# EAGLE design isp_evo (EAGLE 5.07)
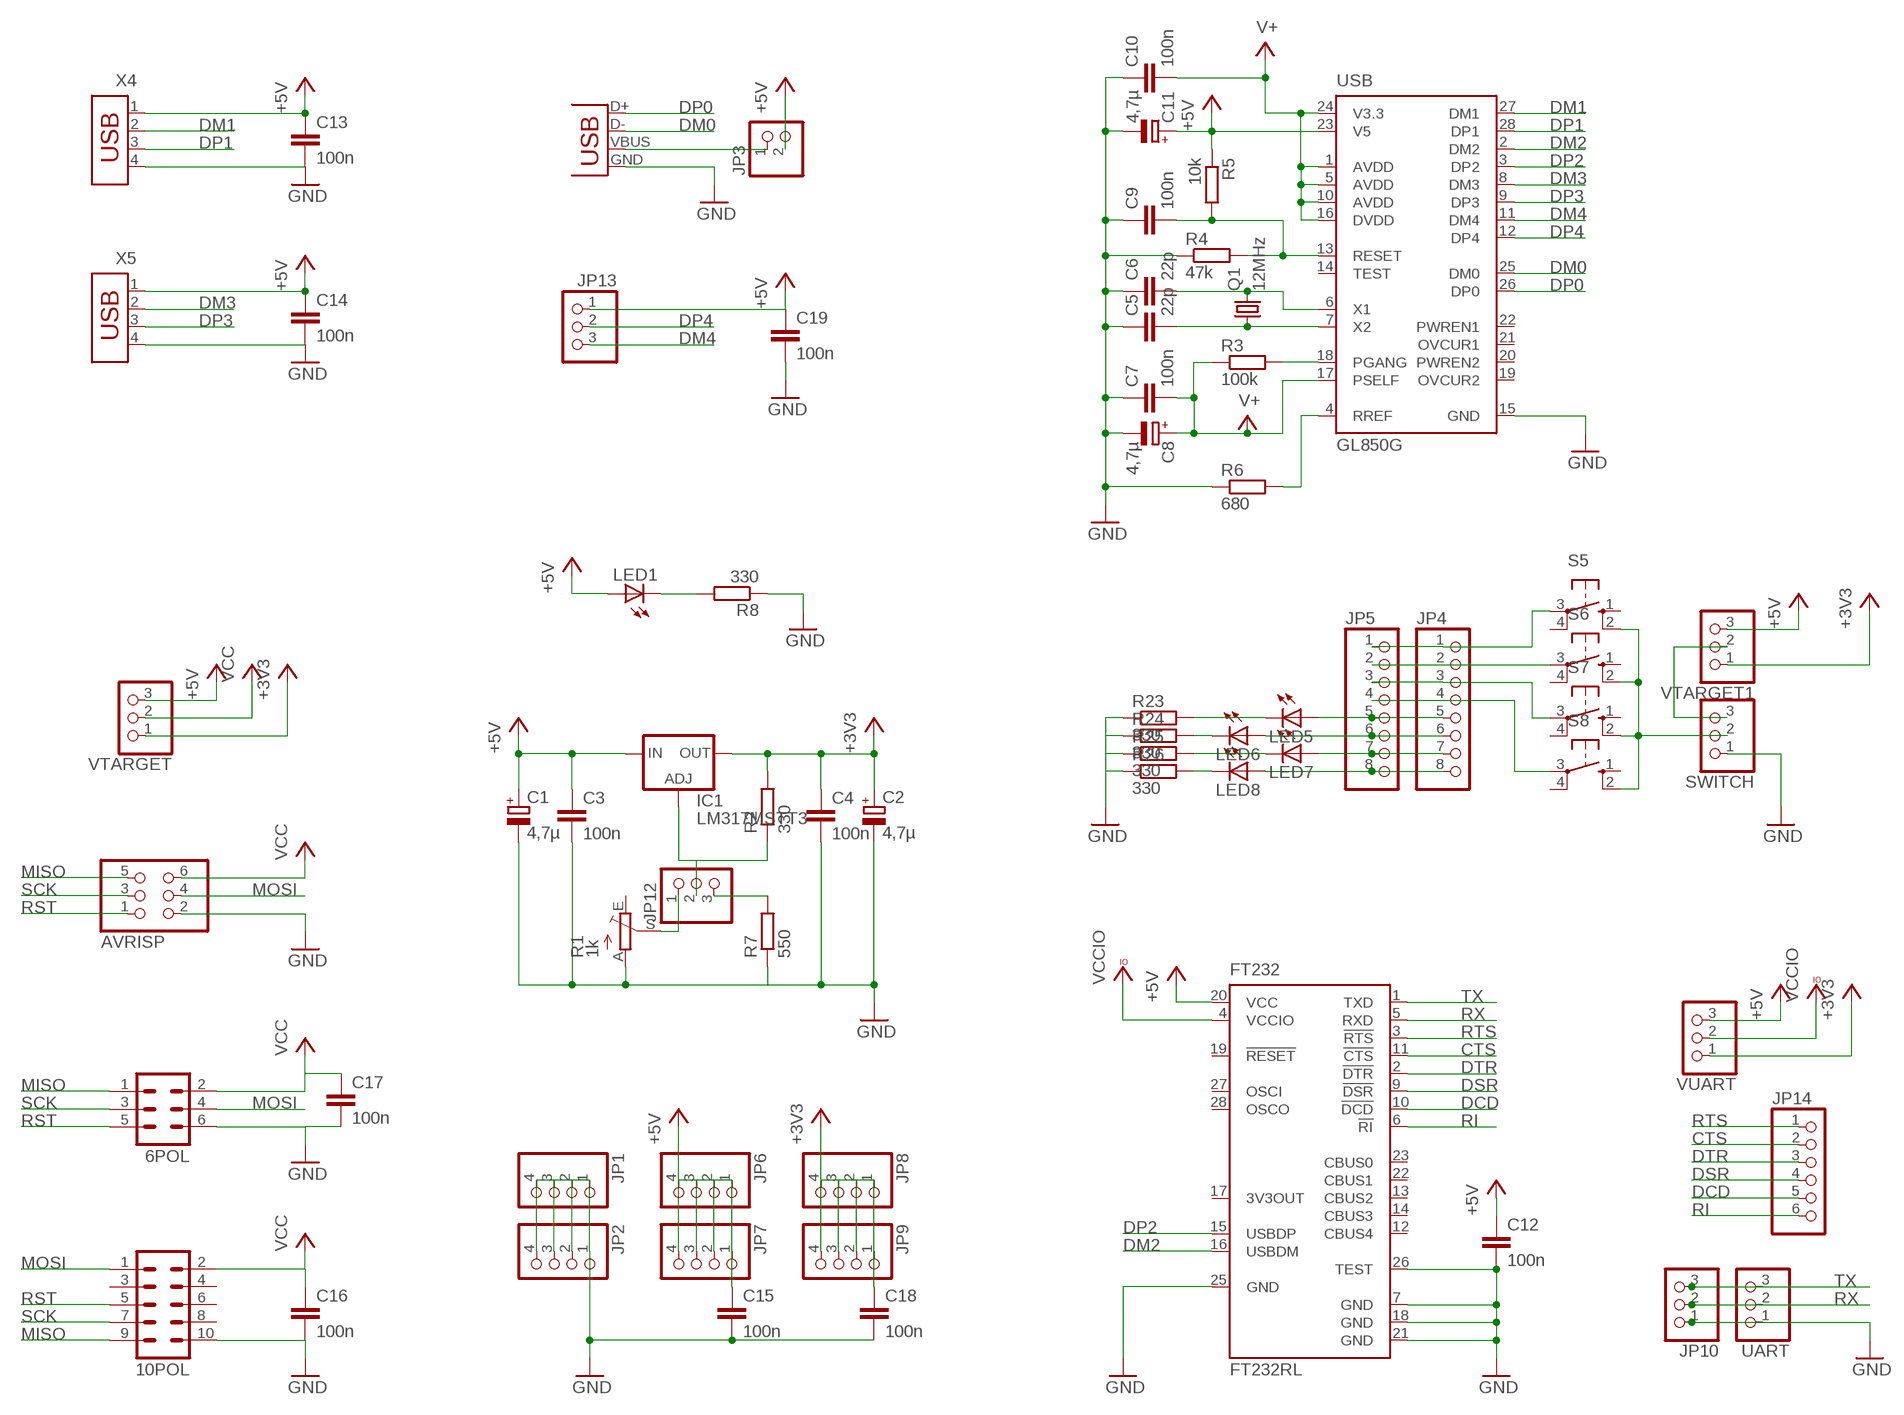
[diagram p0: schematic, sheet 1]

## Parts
6POL  ML6  [ML6]
10POL  ML10  [ML10]
AVRISP  PINHD-2X3  [2X03]
C1  4,7µ  CPOL-EU153CLV-0505  [153CLV-0505]
C2  4,7µ  CPOL-EU153CLV-0505  [153CLV-0505]
C3  100n  C-EUC0805  [C0805]
C4  100n  C-EUC0805  [C0805]
C5  22p  C-EUC0805  [C0805]
C6  22p  C-EUC0805  [C0805]
C7  100n  C-EUC0805  [C0805]
C8  4,7µ  CPOL-EU153CLV-0505  [153CLV-0505]
C9  100n  C-EUC0805  [C0805]
C10  100n  C-EUC0805  [C0805]
C11  4,7µ  CPOL-EU153CLV-0505  [153CLV-0505]
C12  100n  C-EUC0805  [C0805]
C13  100n  C-EUC0805  [C0805]
C14  100n  C-EUC0805  [C0805]
C15  100n  C-EUC0805  [C0805]
C16  100n  C-EUC0805  [C0805]
C17  100n  C-EUC0805  [C0805]
C18  100n  C-EUC0805  [C0805]
C19  100n  C-EUC0805  [C0805]
FT232  FT232RL  [SSOP28]
IC1  LM317MSTT3  [SOT223]
JP1  PINHD-1X4/90  [1X04/90]
JP2  PINHD-1X4  [1X04]
JP3  PINHD-1X2  [1X02]
JP4  PINHD-1X8/90  [1X08/90]
JP5  PINHD-1X8  [1X08]
JP6  PINHD-1X4/90  [1X04/90]
JP7  PINHD-1X4  [1X04]
JP8  PINHD-1X4/90  [1X04/90]
JP9  PINHD-1X4  [1X04]
JP10  PINHD-1X3  [1X03]
JP12  PINHD-1X3  [1X03]
JP13  PINHD-1X3/90  [1X03/90]
JP14  PINHD-1X6  [1X06]
LED1  LEDCHIP-LED0805  [CHIP-LED0805]
LED5  LEDCHIP-LED0805  [CHIP-LED0805]
LED6  LEDCHIP-LED0805  [CHIP-LED0805]
LED7  LEDCHIP-LED0805  [CHIP-LED0805]
LED8  LEDCHIP-LED0805  [CHIP-LED0805]
Q1  12MHz  CRYSTALHC49S  [HC49/S]
R1  1k  TRIM_EU-PT10  [PT-10]
R2  330  R-EU_R0805  [R0805]
R3  100k  R-EU_R0805  [R0805]
R4  47k  R-EU_R0805  [R0805]
R5  10k  R-EU_R0805  [R0805]
R6  680  R-EU_R0805  [R0805]
R7  550  R-EU_R0805  [R0805]
R8  330  R-EU_R0805  [R0805]
R23  330  R-EU_R0805  [R0805]
R24  330  R-EU_R0805  [R0805]
R25  330  R-EU_R0805  [R0805]
R26  330  R-EU_R0805  [R0805]
S5  10-XX  [B3F-10XX]
S6  10-XX  [B3F-10XX]
S7  10-XX  [B3F-10XX]
S8  10-XX  [B3F-10XX]
SWITCH  PINHD-1X3  [1X03]
UART  PINHD-1X3/90  [1X03/90]
USB  GL850G  [SSOP28]
VTARGET  PINHD-1X3  [1X03]
VTARGET1  PINHD-1X3  [1X03]
VUART  PINHD-1X3  [1X03]
X1  USBPTH  [USB-B-PTH]
X4  USB-787616  [USB]
X5  USB-787616  [USB]

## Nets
+3V3: C2.+ C4.1 C18.1 IC1.4(OUT) JP8.1 JP8.2 JP8.3 JP8.4 JP9.1 JP9.2 JP9.3 JP9.4 R2.2 VTARGET1.1 VTARGET.1 VUART.1
+5V: C1.+ C3.1 C11.+ C12.1 C13.1 C14.1 C15.1 C19.1 FT232.20(VCC) IC1.3(IN) JP3.2 JP6.1 JP6.2 JP6.3 JP6.4 JP7.1 JP7.2 JP7.3 JP7.4 JP13.1 LED1.A R5.1 USB.23(V5) VTARGET1.3 VTARGET.3 VUART.3 X4.1 X5.1
CTS: FT232.11(!CTS) JP14.2
DCD: FT232.10(!DCD) JP14.5
DM0: USB.25(DM0) X1.D-
DM1: USB.27(DM1) X4.2
DM2: FT232.16(USBDM) USB.2(DM2)
DM3: USB.8(DM3) X5.2
DM4: JP13.3 USB.11(DM4)
DP0: USB.26(DP0) X1.D+
DP1: USB.28(DP1) X4.3
DP2: FT232.15(USBDP) USB.3(DP2)
DP3: USB.9(DP3) X5.3
DP4: JP13.2 USB.12(DP4)
DSR: FT232.9(!DSR) JP14.4
DTR: FT232.2(!DTR) JP14.3
GND: 6POL.6 10POL.10 AVRISP.2 C1.- C2.- C3.2 C4.2 C5.1 C6.1 C7.1 C8.- C9.1 C10.1 C11.- C12.2 C13.2 C14.2 C15.2 C16.2 C17.2 C18.2 C19.2 FT232.7(GND) FT232.18(GND) FT232.21(GND) FT232.25(GND) FT232.26(TEST) JP1.1 JP1.2 JP1.3 JP1.4 JP2.1 JP2.2 JP2.3 JP2.4 JP10.1 R1.A R4.1 R6.1 R7.1 R8.1 R23.1 R24.1 R25.1 R26.1 SWITCH.1 UART.1 USB.15(GND) X1.GND X4.4 X5.4
MISO: 6POL.1 10POL.9 AVRISP.5
MOSI: 6POL.4 10POL.1 AVRISP.4
N$1: SWITCH.3 VTARGET1.2
N$2: JP12.1 R1.S
N$3: S5.2(S1) S6.2(S1) S7.2(S1) S8.2(S1) SWITCH.2
N$4: IC1.1(ADJ) JP12.2 R2.1
N$5: JP12.3 R7.2
N$6: LED1.C R8.2
N$7: JP3.1 X1.VBUS
N$8: C5.2 Q1.1 USB.7(X2)
N$10: C6.2 Q1.2 USB.6(X1)
N$11: R3.2 USB.18(PGANG)
N$12: C9.2 R4.2 R5.2 USB.13(RESET)
N$15: R6.2 USB.4(RREF)
N$36: JP4.1 JP5.1 S5.3(P)
N$38: JP4.3 JP5.3 S7.3(P)
N$39: JP4.2 JP5.2 S6.3(P)
N$43: JP4.4 JP5.4 S8.3(P)
N$44: LED5.C R23.2
N$45: LED6.C R24.2
N$46: LED7.C R25.2
N$47: LED8.C R26.2
N$50: JP4.7 JP5.7 LED7.A
N$52: JP4.5 JP5.5 LED5.A
N$56: JP4.6 JP5.6 LED6.A
N$59: JP4.8 JP5.8 LED8.A
RI: FT232.6(!RI) JP14.6
RST: 6POL.5 10POL.5 AVRISP.1
RTS: FT232.3(!RTS) JP14.1
RX: FT232.5(RXD) JP10.2 UART.2
SCK: 6POL.3 10POL.7 AVRISP.3
TX: FT232.1(TXD) JP10.3 UART.3
V+: C7.2 C8.+ C10.2 R3.1 USB.1(AVDD) USB.5(AVDD) USB.10(AVDD) USB.16(DVDD) USB.17(PSELF) USB.24(V3.3)
VCC: 6POL.2 10POL.2 AVRISP.6 C16.1 C17.1 VTARGET.2
VCCIO: FT232.4(VCCIO) VUART.2
Unconnected: 10POL.3 10POL.4 10POL.6 10POL.8 FT232.12(CBUS4) FT232.13(CBUS2) FT232.14(CBUS3) FT232.17(3V3OUT) FT232.19(!RESET) FT232.22(CBUS1) FT232.23(CBUS0) FT232.27(OSCI) FT232.28(OSCO) R1.E S5.1(S) S5.4(P1) S6.1(S) S6.4(P1) S7.1(S) S7.4(P1) S8.1(S) S8.4(P1) USB.14(TEST) USB.19(OVCUR2) USB.20(PWREN2) USB.21(OVCUR1) USB.22(PWREN1)

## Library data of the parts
6POL = con-harting-ml:ML6: HARTING
10POL = con-harting-ml:ML10: HARTING
AVRISP = pinhead:PINHD-2X3: PIN HEADER
C1 C2 C8 C11 = rcl:CPOL-EU: POLARIZED CAPACITOR, European symbol
C3-C7 C9 C10 C12-C19 = rcl:C-EU: CAPACITOR, European symbol
FT232 = ftdichip:FT232R: Source: http://www.ftdichip.com/Documents/DataSheets/DS_FT232R_v104.pdf
IC1 = v-reg:LM317?*: 500 mA Adjustable Output Positive Voltage Regulator Source: http://www.onsemi.co.jp .. LM317M-D.PDF
JP1 JP2 JP6-JP9 = pinhead:PINHD-1X4: PIN HEADER
JP3 = pinhead:PINHD-1X2: PIN HEADER
JP4 JP5 = pinhead:PINHD-1X8: PIN HEADER
JP10 JP12 JP13 SWITCH UART VTARGET VTARGET1 VUART = pinhead:PINHD-1X3: PIN HEADER
JP14 = pinhead:PINHD-1X6: PIN HEADER
LED1 LED5-LED8 = led:LED: LED
Q1 = crystal:CRYSTAL: CRYSTAL
R1 = pot:TRIM_EU-: POTENTIOMETER
R2-R8 R23-R26 = rcl:R-EU_: RESISTOR, European symbol
S5-S8 = switch-omron:10-XX: OMRON SWITCH
USB = gl850:GL850G
X1 = SparkFun:USB: USB Connectors USB-B-PTH is fully proven SKU : PRT-00139 USB-miniB is fully proven SKU : PRT-00587 USB-A-PCB is untested. USB-A-H is throughly reviewed, but untested. Spark Fun Electronics SKU : PRT-00437 USB-B-SMT is throughly reviewed, but untested. Needs silkscreen touching up. USB-A-S has not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
X4 X5 = con-amp:USB-787616: AMP connector

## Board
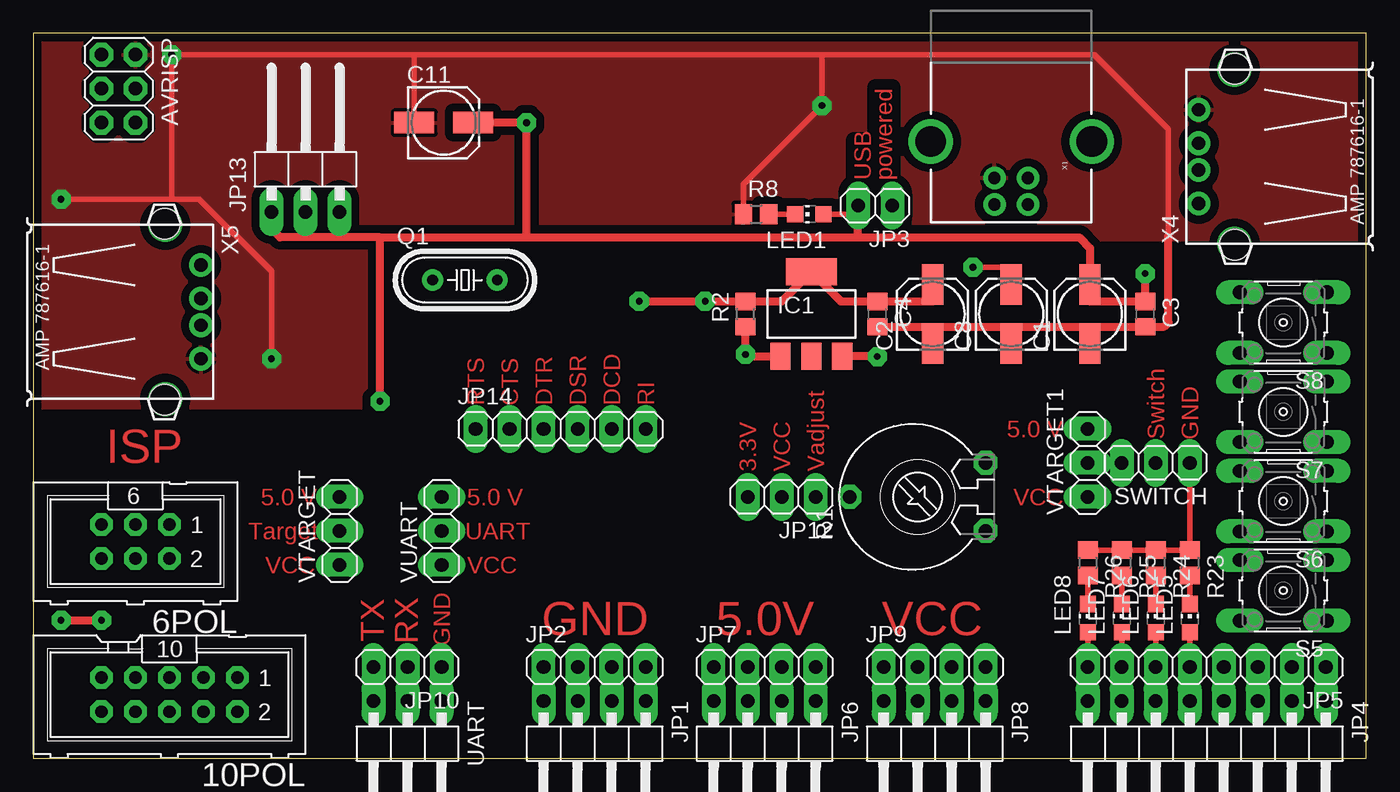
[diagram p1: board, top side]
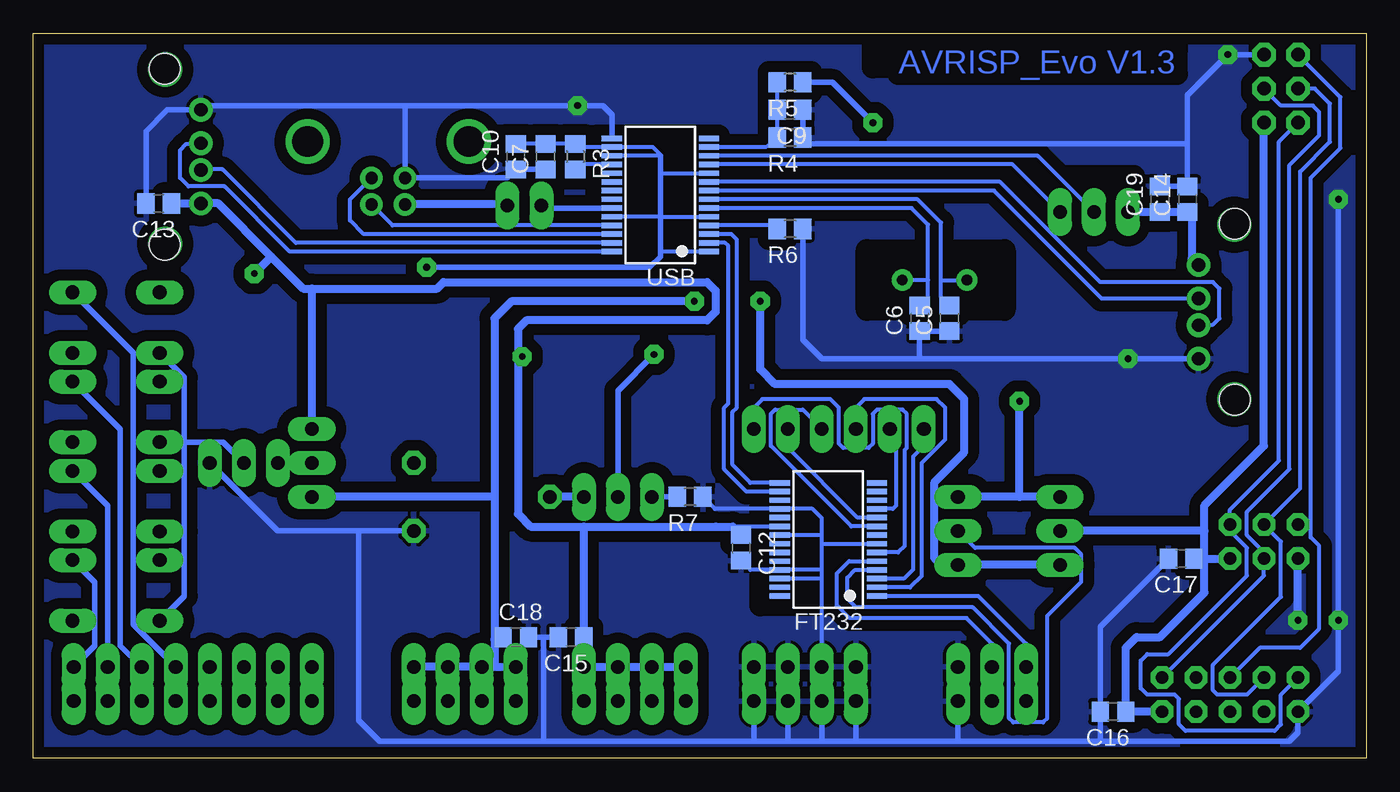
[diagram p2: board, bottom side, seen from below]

Size 99.52 x 54.12 mm. Coordinates in mm from the lower left corner, seen from the top.
Outline: 0,0 99.52,0 99.52,54.12 0,54.12 0,0
Copper layers (1*16): Top 0.035mm / dielectric 1.5mm / Bottom 0.035mm
Design rules "default *": minimum track width 10mil, minimum drill 24mil, track to track 8mil, track to pad 8mil, pad to pad 8mil, via to via 8mil, smd to smd 8mil, copper to edge 10mil, drill to drill 2mil, minimum pad ring 15mil, minimum via ring 8mil, stop-mask expansion 4mil, vias tented up to drill 0mil, thermal gap 10mil
bRestrict: area 27,33.5 to 37.3,37.9; area 49.4,37.6 to 57.5,46.5; area 17.3,41.8 to 23.3,43.5; area 34.9,51.6 to 36.8,53.5; area 61.4,40.6 to 64,42.5; area 36.5,11.4 to 45.2,22.4

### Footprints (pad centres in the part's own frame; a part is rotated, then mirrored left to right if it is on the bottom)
ML6 = drill 0.914 octagon: 1 -2.54,-1.27; 2 -2.54,1.27; 3 0,-1.27; 4 0,1.27; 5 2.54,-1.27; 6 2.54,1.27
ML10 = drill 0.914 octagon: 1 -5.08,-1.27; 2 -5.08,1.27; 3 -2.54,-1.27; 4 -2.54,1.27; 5 0,-1.27; 6 0,1.27; 7 2.54,-1.27; 8 2.54,1.27; 9 5.08,-1.27; 10 5.08,1.27
2X03 = drill 1.016 octagon: 1 -2.54,-1.27; 2 -2.54,1.27; 3 0,-1.27; 4 0,1.27; 5 2.54,-1.27; 6 2.54,1.27
153CLV-0505 = smd 3 x 1.6: + 2.2,0; - -2.2,0
C0805 = smd 1.3 x 1.5: 1 -0.95,0; 2 0.95,0
SSOP28 = smd 0.4 x 1.5: 1 -4.225,-3.625; 2 -3.575,-3.625; 3 -2.925,-3.625; 4 -2.275,-3.625; 5 -1.625,-3.625; 6 -0.975,-3.625; 7 -0.325,-3.625; 8 0.325,-3.625; 9 0.975,-3.625; 10 1.625,-3.625; 11 2.275,-3.625; 12 2.925,-3.625; 13 3.575,-3.625; 14 4.225,-3.625; 15 4.225,3.625; 16 3.575,3.625; 17 2.925,3.625; 18 2.275,3.625; 19 1.625,3.625; 20 0.975,3.625; 21 0.325,3.625; 22 -0.325,3.625; 23 -0.975,3.625; 24 -1.625,3.625; 25 -2.275,3.625; 26 -2.925,3.625; 27 -3.575,3.625; 28 -4.225,3.625
SOT223 = smd 1.5 x 2: 1 -2.3,-3.15; 2 0,-3.15; 3 2.3,-3.15 | smd 3.8 x 2: 4 0,3.15
1X04/90 = drill 1.016 long: 1 -3.81,-3.81; 2 -1.27,-3.81; 3 1.27,-3.81; 4 3.81,-3.81
1X04 = drill 1.016 long: 1 -3.81,0; 2 -1.27,0; 3 1.27,0; 4 3.81,0
1X02 = drill 1.016 long: 1 -1.27,0; 2 1.27,0
1X08/90 = drill 1.016 long: 1 -8.89,-3.81; 2 -6.35,-3.81; 3 -3.81,-3.81; 4 -1.27,-3.81; 5 1.27,-3.81; 6 3.81,-3.81; 7 6.35,-3.81; 8 8.89,-3.81
1X08 = drill 1.016 long: 1 -8.89,0; 2 -6.35,0; 3 -3.81,0; 4 -1.27,0; 5 1.27,0; 6 3.81,0; 7 6.35,0; 8 8.89,0
1X03 = drill 1.016 long: 1 -2.54,0; 2 0,0; 3 2.54,0
1X03/90 = drill 1.016 long: 1 -2.54,-3.81; 2 0,-3.81; 3 2.54,-3.81
1X06 = drill 1.016 long: 1 -6.35,0; 2 -3.81,0; 3 -1.27,0; 4 1.27,0; 5 3.81,0; 6 6.35,0
CHIP-LED0805 = smd 1.2 x 1.2: A 0,-1.05; C 0,1.05
HC49/S = drill 0.813 round: 1 -2.413,0; 2 2.413,0
PT-10 = drill 1.016 octagon: A -2.54,-5.08; E 2.54,-5.08; S 0,5.08
R0805 = smd 1.3 x 1.5: 1 -0.95,0; 2 0.95,0
B3F-10XX = drill 1.016 long: 1 -3.251,2.261; 2 3.251,2.261; 3 -3.251,-2.261; 4 3.251,-2.261
USB-B-PTH = drill 0.914 pad 1.676 round: D+ 0,1.25; D- 1.981,1.25; GND 0,-1.25; VBUS 1.981,-1.25 | drill 2.286 round: S1 -2.718,-6.02; S2 -2.718,6.02
USB = drill 1 round: 1 -3.5,12.99; 2 -1,12.99; 3 1,12.99; 4 3.5,12.99 | hole 2.3: -6.57,10.28; 6.57,10.28

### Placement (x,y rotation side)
6POL  7.62,16.19 180 top
10POL  10.16,4.76 180 top
AVRISP  6.35,50.01 270 top
C1  78.9,33.18 90 top
C2  67.15,33.18 90 top
C3  83.03,33.18 270 top
C4  63.02,33.18 270 top
C5  31.11,32.86 90 bottom
C6  33.34,32.86 90 bottom
C7  61.28,44.93 90 bottom
C8  73.03,33.18 90 top
C9  43.02,48.42 180 bottom
C10  63.5,44.93 90 bottom
C11  30.64,47.47 0 top
C12  46.67,15.72 270 bottom
C13  90.17,41.43 180 bottom
C14  13.33,41.75 90 bottom
C15  59.37,9.05 180 bottom
C16  18.89,3.49 180 bottom
C17  13.81,14.92 180 bottom
C18  63.5,9.05 0 bottom
C19  15.4,41.75 90 bottom
FT232  40.16,16.35 90 bottom
IC1  58.1,33.18 0 top
JP1  41.91,0.48 180 top
JP2  41.91,6.83 0 top
JP3  62.87,41.27 180 top
JP4  87.63,0.48 180 top
JP5  87.63,6.83 180 top
JP6  54.61,0.48 180 top
JP7  54.61,6.83 0 top
JP8  67.31,0.48 180 top
JP9  67.31,6.83 0 top
JP10  27.94,6.83 180 top
JP12  55.88,19.53 180 top
JP13  20.32,44.61 0 top
JP14  39.37,24.61 0 top
LED1  57.94,40.64 90 top
LED5  86.36,10.48 0 top
LED6  83.82,10.48 0 top
LED7  81.28,10.48 0 top
LED8  78.74,10.48 0 top
Q1  32.23,35.72 0 top
R1  66.04,19.53 90 top
R2  53.18,33.18 90 top
R3  59.06,44.93 270 bottom
R4  43.02,46.35 180 bottom
R5  43.02,50.48 180 bottom
R6  43.02,39.53 180 bottom
R7  50.48,19.53 180 bottom
R8  53.98,40.64 0 top
R23  86.36,14.61 270 top
R24  83.82,14.61 270 top
R25  81.28,14.61 270 top
R26  78.74,14.61 270 top
S5  93.35,12.54 180 top
S6  93.35,19.21 180 top
S7  93.35,25.88 180 top
S8  93.35,32.54 180 top
SWITCH  83.82,22.07 180 top
UART  27.94,0.48 180 top
USB  52.71,42.07 90 bottom
VTARGET  22.86,16.99 90 top
VTARGET1  78.74,22.07 90 top
VUART  30.48,16.99 90 top
X1  73.02,43.34 270 top
X4  100.01,44.93 90 top
X5  -0.48,33.34 270 top

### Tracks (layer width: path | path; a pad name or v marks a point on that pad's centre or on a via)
+3V3  (via drill 0.5 pad 1.42)
  Top 0.61: C2.+ 67.15,34.13 C4.1 60.3,34.13 IC1.4 55.9,34.13 R2.2 v50.16,34.13 v45.24,34.13 v45.25,34.13
  Bottom 0.61: JP9.4 JP8.1 | JP9.4 | JP9.3 JP9.4 | JP9.2 JP9.3 | 65.09,6.83 JP9.1 | 65.09,6.83 JP9.2 | JP9.1 JP8.4 | JP9.1 | JP9.2 JP8.3 | JP9.2 | JP9.3 JP8.2 | JP9.3 | VTARGET.1 VUART.1 | VUART.1 | VUART.1 31.75,14.45 32.23,14.92 32.23,20.64 30,22.86 30,26.83 31.11,27.94 44.13,27.94 45.24,29.05 v45.24,34.13 | 65.09,8.89 65.09,6.83 | C18.1 64.45,8.89 65.09,8.89 | 65.09,19.53 VTARGET1.1 | 65.09,19.53 65.09,8.89 | v50.16,34.13 63.82,34.13 65.09,32.86 65.09,19.53
+5V  (via drill 0.5 pad 1.42)
  Top 0.406: JP3.2 | LED1.A 60.96,40.64 JP3.2
  Top 0.61: 62.94,30.09 v63.02,30 63,30.03 IC1.3 | v36.83,47.47 C11.+ | v36.83,47.47 | 36.83,38.89 61.59,38.89 | 36.83,38.89 v36.83,47.47 | 25.88,38.89 36.83,38.89 | JP13.1 17.78,39.53 18.41,38.89 25.88,38.89 | JP13.1 | 61.59,38.89 JP3.2 | 61.59,38.89 78.11,38.89 78.9,38.1 C1.+ 78.9,34.13 C3.1 v83.03,36.2 | v83.03,36.2 | v25.88,26.67 25.88,38.89
  Bottom 0.305: FT232.20 48.55,17.33 48.58,17.3
  Bottom 0.406: USB.23 61.41,41.09 JP3.2 | R5.1 39.85,50.48 v36.83,47.47 | 63.34,30 v63.02,30
  Bottom 0.61: JP7.1 JP6.4 | JP7.1 | JP7.2 JP6.3 | JP7.2 | JP7.3 JP6.2 | JP7.3 | JP7.4 JP6.1 | JP7.4 | JP7.1 | JP7.2 JP7.1 | JP7.2 | JP7.3 JP7.2 | JP7.4 JP7.3 | VTARGET.3 25.88,19.53 | VUART.3 | v36.83,47.47 | 58.42,17.3 62.39,17.3 63.34,18.26 63.34,30 63.34,32.07 62.71,32.7 49.21,32.7 48.58,33.34 48.58,34.92 49.21,35.56 68.9,35.56 69.37,35.08 78.74,35.08 | JP7.4 C15.1 58.42,17.3 | 58.42,17.3 48.58,17.3 47.31,17.3 C12.1 | v36.83,47.47 | 81.76,37.47 85.72,41.43 X4.1 C13.1 | v83.03,36.2 81.76,37.47 | 81.76,37.47 | 81.76,37.47 79.38,35.08 78.74,35.08 | 78.74,35.08 VTARGET1.3 | JP13.1 C19.1 C14.1 13.34,40.64 13.02,40.32 13.02,37.34 X5.1 | 25.88,19.53 v25.88,26.67 | 25.88,19.53 VUART.3
CTS
  Bottom 0.305: FT232.11 35.35,18.63 35.08,18.89 35.08,24.13 JP14.2
DCD
  Bottom 0.305: JP14.5 43.18,23.18 37.98,17.98 FT232.10
DM0
  Bottom 0.305: USB.25 72.71,39.79 X1.D-
DM1
  Bottom 0.305: USB.27 79.93,38.49 85.41,43.97 86.97,43.97 X4.2
DM2
  Bottom 0.305: USB.2 47.86,38.49 47.62,38.26 47.62,26.51 47.94,26.19 47.94,21.59 46.28,19.93 FT232.16
DM3
  Bottom 0.305: X5.2 19.73,34.34 27.79,42.39 USB.8
DM4
  Bottom 0.305: USB.11 26.41,44.34 JP13.3
DP0
  Bottom 0.305: USB.26 74.86,39.14 75.88,40.16 75.88,41.73 X1.D+
DP1
  Bottom 0.305: USB.28 80.39,37.84 85.25,42.7 87.95,42.7 88.58,43.34 88.58,45.4 88.11,45.88 87.07,45.88 X4.3
DP2
  Bottom 0.305: USB.3 47.4,39.14 46.99,38.73 46.99,26.19 47.31,25.88 47.31,21.91 45.98,20.58 FT232.15
DP3
  Bottom 0.305: USB.9 27.33,43.04 19.84,35.56 11.43,35.56 10.95,35.08 10.95,32.86 11.43,32.38 12.47,32.38 X5.3
DP4
  Bottom 0.305: USB.12 24.52,44.99 JP13.2
DSR
  Bottom 0.305: JP14.4 42.07,26.04 44.13,26.04 44.45,25.72 44.45,23.34 38.44,17.33 FT232.9
DTR
  Bottom 0.305: FT232.2 34.05,12.78 33.18,13.65 33.18,22.07 31.43,23.81 31.43,26.19 32.07,26.83 37.47,26.83 38.1,26.19 JP14.3 | JP14.3
GND  (via drill 0.5 pad 1.42)
  Top 0.406: R23.1 | R25.1 R24.1 R23.1 | R25.1 | R25.1 R26.1 | R26.1 | 58.9,52.55 59.69,52.55 | v2.06,41.75 10.32,41.75 | 10.32,41.75 v10.32,52.55 28.44,52.55 | 84.77,39.05 84.77,46.99 79.22,52.55 59.74,52.55 | 58.9,52.55 v58.9,48.74 53.02,42.87 R8.1 | SWITCH.1 R23.1 | SWITCH.1 | 28.44,52.55 C11.- | 28.44,52.55 58.9,52.55 | v17.78,29.84 17.78,36.35 12.38,41.75 10.32,41.75
  Top 0.61: v2.06,10.32 v5.08,10.32 | 67.15,32.23 73.03,32.23 | 78.9,32.23 C3.2 | C3.2 | 67.15,32.23 C2.- | C4.2 67.15,32.23 | 73.03,32.23 C8.- | 78.9,32.23 C1.- | 73.03,32.23 78.9,32.23 | C3.2 84.46,32.23 84.77,32.54 84.77,39.05
  Bottom 0.305: 40.64,14.08 40.64,16.03 | 40.64,16.68 40.64,17.94 41.33,18.63 FT232.18 48.63,18.63 R7.1 | 40.64,16.68 FT232.21 | 40.64,16.03 FT232.7 | 40.64,16.03 40.64,16.68 | 40.64,14.08 FT232.25 45.98,14.08 C12.2 | 40.64,13.43 40.64,14.08 | 40.64,13.43 FT232.26 | JP2.2 | JP2.2 40.64,13.43 | JP2.2 | v58.9,48.74 59.69,48.74 | JP2.3 | JP2.1
  Bottom 0.406: 38.1,1.27 40.64,1.27 | JP10.1 UART.1 30.48,1.27 | JP1.4 JP2.1 38.1,1.27 | JP1.3 JP2.2 40.64,1.27 | JP1.2 JP2.3 43.18,1.27 | JP1.1 JP2.4 45.72,1.27 | 30.48,1.27 38.1,1.27 | 40.64,1.27 43.18,1.27 | 43.18,1.27 45.72,1.27 | 60.48,9.05 C15.2 | 45.72,1.27 61.44,1.27 | 60.48,9.05 | 61.44,9.05 60.48,9.05 | 61.44,1.27 61.44,9.05 | 61.44,9.05 C18.2 | 19.84,1.27 C16.2 | 19.84,1.27 30.48,1.27 | C16.2 | 10POL.10 2.06,6.51 v2.06,10.32 v2.06,41.75 | 19.84,1.27 5.71,1.27 5.08,1.91 10POL.10 | 10POL.10 | C7.1 C10.1 64.14,43.34 X1.GND 71.78,48.74 | v10.32,52.55 AVRISP.2 | v10.32,52.55 | R6.1 42.07,31.27 40.64,29.84 33.34,29.84 | C16.2 19.84,9.84 C17.2 | R4.1 42.07,46.2 41.75,45.88 13.34,45.88 | R4.1 C9.1 | R4.1 | C5.1 C6.1 33.34,29.84 | v58.9,48.74 58.87,48.71 | USB.15 56.33,48.08 56.99,48.74 v58.9,48.74 | 61.44,1.27 73.66,1.27 75.25,2.86 75.25,16.99 | 75.25,16.99 81.28,16.99 SWITCH.1 | 75.25,16.99 R1.A | 71.78,48.74 86.71,48.74 X4.4 89.53,48.43 91.12,46.83 C13.2 | v58.9,48.74 71.78,48.74 | 13.34,45.88 C14.2 | v10.32,52.55 13.34,49.53 13.34,45.88 | C14.2 C19.2 | C14.2 | v17.78,29.84 | 17.46,29.84 12.52,29.84 X5.4 | 17.46,29.84 33.34,29.84 | v17.78,29.84 17.46,29.84
  Bottom 0.61: v5.08,10.32 6POL.6
  pour Bottom (isolate 0.813): -0.48,54.61 100.01,54.61 100.01,-0.48 -0.48,-0.48
  pour Top (isolate 0.61): -0.48,54.61 100.01,54.61 100.01,38.73 26.19,38.73 26.19,26.19 -0.48,26.19
MISO
  Bottom 0.305: 10POL.9 6.35,4.76 6.35,2.54 6.83,2.06 13.49,2.06 13.97,2.54 13.97,4.45 14.29,4.76 16.35,4.76 16.83,5.24 16.83,7.3 16.35,7.78 14.76,7.78 8.89,13.65 8.89,15.72 10.16,16.99 6POL.1 10.16,18.57 6.51,22.23 6.51,46.04 AVRISP.5
MOSI
  Bottom 0.305: AVRISP.4 6.35,48.74 3.97,48.74 3.49,48.26 3.49,46.51 5.71,44.29 5.71,21.59 8.89,18.41 8.89,16.67 7.62,15.4 6POL.4 7.62,13.65 10POL.1
N$1
  Bottom 0.61: SWITCH.3 VTARGET1.2 | SWITCH.3
N$2
  Bottom 0.61: JP12.1 R1.S | R1.S
N$3
  Bottom 0.406: S5.2 88.27,12.11 88.27,16.95 | 88.27,23.62 88.27,28.45 S8.2 | 88.27,23.62 S7.2 | 88.27,16.95 88.27,23.62 | 88.27,16.95 S6.2 | SWITCH.2 85.37,23.62 88.27,23.62
N$4  (via drill 0.5 pad 1.42)
  Top 0.406: IC1.1 55.88,29.95 | R2.1
  Top 0.61: R2.1 v53.18,30.16 53.31,30.03 IC1.1
  Bottom 0.406: JP12.2 55.88,27.46 v53.18,30.16
N$5
  Bottom 0.406: R7.2 JP12.3 | R7.2
N$6
  Top 0.406: R8.2 | R8.2 LED1.C
N$7
  Bottom 0.61: X1.VBUS 64.14,41.36 JP3.1
N$8
  Bottom 0.305: USB.7 33.49,41.74 31.75,40.01 31.75,35.72 | C5.2 31.75,34.45 31.75,35.72 | 31.75,35.72 Q1.1
N$9  (via drill 1.4 pad 2.54)
  other vias: 9.84,26.83
N$10
  Bottom 0.305: USB.6 33.95,41.09 32.7,39.85 32.7,35.72 | C6.2 32.7,34.45 32.7,35.72 | 32.7,35.72 Q1.2
N$11
  Bottom 0.305: USB.18 58.69,44.34 R3.2
N$12
  Bottom 0.305: USB.13 44.84,45.64 R4.2 | R4.2 C9.2 | R4.2 | C9.2 R5.2 | C9.2
N$13  (via drill 1.4 pad 2.54)
  other vias: 9.84,39.85
N$14  (via drill 1.4 pad 2.54)
  other vias: 89.69,38.42
N$15
  Bottom 0.305: USB.4 44.24,39.79 R6.2
N$16  (via drill 1.4 pad 2.54)
  other vias: 89.69,51.44
N$36
  Bottom 0.406: S5.3 94.93,13.14 94.93,8.41 JP5.1 JP4.1
N$38
  Bottom 0.406: S7.3 93.03,24.57 93.03,8.41 JP5.3 JP4.3
N$39
  Bottom 0.406: S6.3 93.98,18.85 JP5.2 JP4.2
N$43
  Bottom 0.406: S8.3 92.08,30.28 92.08,10 JP5.4 JP4.4
N$44
  Top 0.406: LED5.C R23.2
N$45
  Top 0.406: R24.2 LED6.C
N$46
  Top 0.406: LED7.C R25.2
N$47
  Top 0.406: LED8.C R26.2 | LED8.C
N$50
  Top 0.406: JP4.7 LED7.A | JP4.7
  Bottom 0.406: JP4.7 JP5.7
N$52
  Top 0.406: JP4.5 LED5.A | JP4.5
  Bottom 0.406: JP4.5 JP5.5
N$56
  Top 0.406: JP4.6 LED6.A | JP4.6
  Bottom 0.406: JP4.6 JP5.6
N$59
  Top 0.406: JP4.8 LED8.A | JP4.8
  Bottom 0.406: JP4.8 JP5.8
RI
  Bottom 0.305: FT232.6 34.95,15.38 34.45,15.88 34.45,23.02 34.29,23.18 34.29,25.72 34.61,26.04 36.51,26.04 36.83,25.72 36.83,23.5 37.15,23.18 39.05,23.18 39.37,23.5 39.37,26.19 40.01,26.83 45.09,26.83 45.72,26.19 JP14.6 | JP14.6
RST
  Bottom 0.305: AVRISP.1 1.91,49.37 1.91,45.56 4.13,43.34 4.13,17.62 4.13,17.46 | 10POL.5 7.94,8.26 4.92,8.26 3.49,9.68 3.49,15.88 4.13,16.51 4.13,17.46 | 4.13,17.46 6POL.5
RTS
  Bottom 0.305: FT232.3 34.52,13.43 33.81,14.13 33.81,22.54 33.02,23.34 JP14.1 | JP14.1
RX
  Bottom 0.305: FT232.5 38.61,14.73 39.53,13.81 39.53,11.43 38.58,10.48 29.84,10.48 27.94,8.57 JP10.2
  Bottom 0.406: UART.2 JP10.2
SCK
  Bottom 0.305: AVRISP.3 3.81,50.01 2.7,48.9 2.7,46.04 4.92,43.81 4.92,20.16 5.87,19.21 6.19,18.89 6POL.3 6.35,16.19 6.35,12.06 11.43,6.99 11.43,5.08 11.11,4.76 8.89,4.76 10POL.7 | AVRISP.3
TX
  Bottom 0.305: FT232.1 28.95,12.13 25.4,8.57 JP10.3
  Bottom 0.406: UART.3 JP10.3
V+  (via drill 0.5 pad 1.42)
  Top 0.406: v70.17,36.67 | v70.17,36.67 73.03,36.67 C8.+
  Bottom 0.305: USB.17 52.7,44.99 52.7,45.09 53.26,45.64 USB.16 58.82,45.64 R3.1 C7.2 C10.2 | USB.1 52.7,37.84 52.7,38.26 | 52.7,40.44 USB.24 | USB.10 52.7,43.69 52.7,43.66 | 52.7,40.44 USB.5 | 52.7,40.48 52.7,40.44
  Bottom 0.406: 52.7,44.99 52.7,43.66 52.7,40.48 52.7,38.26 52.7,37.47 53.5,36.67 v70.17,36.67
VCC
  Bottom 0.406: 12.06,14.92 C17.1
  Bottom 0.61: C16.1 | 10POL.2 C16.1 | C16.1 | AVRISP.6 7.62,23.34 12.06,18.89 12.06,16.99 | 12.06,14.92 12.06,12.38 15.4,9.05 17.14,9.05 17.94,8.26 C16.1 | 12.06,16.99 VTARGET.2 | 12.06,14.92 6POL.2 | 12.06,14.92 12.06,16.99
VCCIO
  Bottom 0.305: FT232.4 38.15,14.08 38.73,13.49 38.73,11.91 38.1,11.27 29.37,11.27 26.67,8.57 26.67,3.02 26.35,2.7 24.13,2.7 23.81,3.02 23.81,10.64 21.27,13.18 21.27,15.24 21.75,15.72 29.21,15.72 VUART.2

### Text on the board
Top: USB | powered | RTS | CTS | DTR | DSR | DCD | RI | 5.0 V | Switch | GND | ISP | 3.3V | VCC | Vadjust | 5.0 V | 5.0 V | VCC | Target | UART | VCC | VCC | TX | RX | GND | 5.0V | VCC | GND
Bottom: AVRISP_Evo V1.3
